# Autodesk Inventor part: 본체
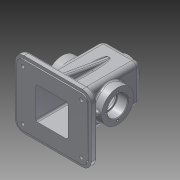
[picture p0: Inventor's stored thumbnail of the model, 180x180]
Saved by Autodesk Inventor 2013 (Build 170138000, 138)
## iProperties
Created: 2016-01
Part Number: 본체
Material: 알루미늄 6061
Document SubType Name: Modeling
Designer: User
Density: 2.71 g/cm^3
Mass: 889.915 g
Surface Area: 961.713 cm^2
Volume: 328.382 cm^3
Author: User
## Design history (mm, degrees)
sketch "스케치1"
  geometry: L1 (-32.5, 55)-(32.5, 55); L2 (32.5, 55)-(32.5, -55); L3 (32.5, -55)-(-32.5, -55); L4 (-32.5, -55)-(-32.5, 55); 1 further point
  constraints: 8 end point, 2 parallel, 1 horizontal, 1 perpendicular
  dimensions: "d0" = 65 distance of L1.start L1.end; "d2" = 110 distance of L3.end L1.start; "d3" = 32.5 distance from line of point (0, 0) L4; "d4" = 55 distance from line of point (0, 0) L1
extrude "돌출1" new body sketch "스케치1" stored distance "d5" = 65; taper "d6" = 0 deg
sketch "스케치2"
  geometry: L1 (65, 0)-(65, -65) reference; L2 (0, 0)-(65, 0) reference; L3 (0, 0)-(0, -65) reference; L4 (65, -65)-(0, -65) reference; L5 (5, -5)-(60, -5); L6 (60, -5)-(60, -60); L7 (60, -60)-(5, -60); L8 (5, -60)-(5, -5); 1 further point
  constraints: 8 end point, 2 parallel, 1 horizontal, 1 perpendicular
  dimensions: "d7" = 5 distance between parallel lines of L8 L3; "d8" = 5 distance between parallel lines of L2 L5; "d9" = 5 distance between parallel lines of L1 L6; "d10" = 5 distance between parallel lines of L4 L7
extrude "돌출2" cut sketch "스케치2" distance "d11" = 105; taper "d12" = 0 deg
node "작업 평면1"
sketch "스케치3"
  geometry: C1 r 20 at (32.5, 32.5); 1 further point
  constraints: 1 centre point, 1 coincident
  dimensions: "d14" = 40 diameter of C1
extrude "돌출3" join sketch "스케치3" stored distance "d15" = 105; taper "d16" = 0 deg
hole "구멍1" diameter "d19" = 21; stored, may be unused: countersink angle "d23" = 90 deg, drill point angle "d25" = 118 deg; dims "d17" = 10, "d18" = 10, "d20" = 6, "d21" = 4, "d22" = 2, "d24" = 8
node "작업 평면2"
sketch "스케치5"
  geometry: C1 r 27.5 at (32.5, 55); 1 further point
  constraints: 1 centre point, 1 coincident
  dimensions: "d28" = 55 diameter of C1
extrude "돌출4" join sketch "스케치5" stored distance "d29" = 105; taper "d30" = 0 deg
hole "구멍2" diameter "d33" = 35; stored, may be unused: countersink angle "d37" = 90 deg, drill point angle "d39" = 0 deg; dims "d31" = 10, "d32" = 10, "d34" = 6, "d35" = 4, "d36" = 2, "d38" = 17
hole "구멍3" diameter "d42" = 30; stored, may be unused: countersink angle "d46" = 90 deg, drill point angle "d48" = 0 deg; dims "d40" = 10, "d41" = 10, "d43" = 6, "d44" = 4, "d45" = 2, "d47" = 17
node "작업 평면3"
sketch "스케치6"
  geometry: L1 (-65, 57.5)-(65, 57.5); L2 (65, 57.5)-(65, -57.5); L3 (65, -57.5)-(-65, -57.5); L4 (-65, -57.5)-(-65, 57.5); 1 further point
  constraints: 8 end point, 2 parallel, 1 horizontal, 1 perpendicular
  dimensions: "d50" = 130 distance of L1.start L1.end; "d52" = 115 distance of L1.end L2.end; "d53" = 65 distance from line of point (0, 0) L4; "d54" = 57.5 distance from line of point (0, 0) L1
extrude "돌출5" join sketch "스케치6" distance "d55" = 10; taper "d56" = 0 deg
node "작업 평면4"
sketch "스케치8"
  geometry: L1 (-60, 52.5)-(60, 52.5); L2 (60, 52.5)-(60, -52.5); L3 (60, -52.5)-(-60, -52.5); L4 (-60, -52.5)-(-60, 52.5); L5 (65, -57.5)-(65, 57.5) reference; L6 (65, 57.5)-(-65, 57.5) reference; L7 (-27.5, 27.5)-(27.5, 27.5); L8 (27.5, 27.5)-(27.5, -27.5); L9 (27.5, -27.5)-(-27.5, -27.5); L10 (-27.5, -27.5)-(-27.5, 27.5); 1 further point
  constraints: 16 end point, 4 parallel, 2 horizontal, 2 perpendicular
  dimensions: "d61" = 120 distance of L1.start L1.end; "d63" = 105 distance of L1.end L2.end; "d64" = 5 distance between parallel lines of L5 L2; "d65" = 5 distance between parallel lines of L6 L1; "d66" = 55 distance of L7.start L7.end; "d67" = 55 distance of L7.end L8.end; "d68" = 27.5 distance from line of point (0, 0) L7; "d70" = 27.5 distance from line of point (0, 0) L10
extrude "돌출6" join sketch "스케치8" stored distance "d71" = 10; taper "d72" = 0 deg
extrude "돌출7" cut sketch "스케치8" distance "d73" = 89.75; taper "d74" = 0 deg
sketch "스케치9"
  geometry: L1 (-53, 57.5)-(-63, 57.5) reference; L2 (-53, 57.5)-(-53, -57.5) reference; L3 (55, 32.5)-(-53, 32.5) reference; L4 (-53, 47.5)-(32.069, 32.5); 1 further point
  constraints: 2 end point, 2 point on line
  dimensions: "d79" = 10 distance from line of L1 L4.start; "d80" = 10 deg angle of L1 L4
feature "리브1" sketch "스케치9" dims "d81" = 1, "d82" = 10, "d83" = 0, "d84" = 0, "d85" = 1, "d86" = 1
sketch "스케치11"
  geometry: L1 (-27.5, -65)-(-27.5, 50) reference; L2 (-65, -53)-(65, -53) reference; L3 (-42.5, -53)-(-42.5, -22.279); 1 further point
  constraints: 2 end point, 1 perpendicular, 1 point on line
  dimensions: "d87" = 15 distance from line of L1 L3.start
feature "리브2" sketch "스케치11" dims "d88" = 1, "d89" = 6, "d90" = 0, "d91" = 0, "d92" = 1, "d93" = 1
sketch "스케치12"
  geometry: L1 (-65, 57.5)-(65, 57.5) reference; C1 r 7.5 at (-50, 42.5); C2 r 7.5 at (50, 42.5); C3 r 7.5 at (50, -42.5); C4 r 7.5 at (-50, -42.5); 1 further point
  constraints: 4 centre point, 1 horizontal alignment
  dimensions: "d94" = 15 diameter of C1; "d95" = 15 diameter of C2; "d96" = 15 diameter of C3; "d97" = 15 diameter of C4; "d99" = 15 distance from line of C1.centre L1; "d100" = 100 distance of C2.centre C1.centre; "d102" = 85 distance of C4.centre C1.centre; "d103" = 100 distance of C3.centre C4.centre; "d105" = 42.5 vertical distance of point (0, 0) C2.centre; "d106" = 50 horizontal distance of C3.centre point (0, 0); "d187" = 50 horizontal distance of point (0, 0) C1.centre
extrude "돌출8" join sketch "스케치12" distance "d107" = 3; taper "d108" = 0 deg
hole "구멍4" diameter "d111" = 6; stored, may be unused: countersink angle "d115" = 90 deg, drill point angle "d117" = 0 deg; dims "d109" = 10, "d110" = 10, "d112" = 6, "d113" = 4, "d114" = 2, "d116" = 17
hole "구멍5" diameter "d120" = 6; stored, may be unused: countersink angle "d124" = 90 deg, drill point angle "d126" = 0 deg; dims "d118" = 10, "d119" = 10, "d121" = 6, "d122" = 4, "d123" = 2, "d125" = 17
hole "구멍6" diameter "d129" = 6; stored, may be unused: countersink angle "d133" = 90 deg, drill point angle "d135" = 0 deg; dims "d127" = 10, "d128" = 10, "d130" = 6, "d131" = 4, "d132" = 2, "d134" = 17
hole "구멍7" diameter "d138" = 6; stored, may be unused: countersink angle "d142" = 90 deg, drill point angle "d144" = 0 deg; dims "d136" = 10, "d137" = 10, "d139" = 6, "d140" = 4, "d141" = 2, "d143" = 17
node "작업 평면7"
feature "면 기울기1" dims angle "d145" = 5 deg
sketch "스케치13"
  geometry: L1 (-78.073, 0)-(132.155, 0); C1 r 10.5 at (0, 0) reference; C2 r 20 at (0, 0) reference; C3 r 1.5 at (0, 14.5); C4 r 1.5 at (-14.5, 0); C5 r 1.5 at (0, -14.5); C6 r 1.5 at (14.5, 0)
  constraints: 4 centre point, 2 end point, 1 horizontal, 1 point on line, 1 vertical alignment, 9 other
  dimensions: "d146" = 3 diameter of C3; "d147" = 29 diameter of C3.centre L1; "d150" = 360 deg dimension on C2.centre C3.centre (derived)
hole "구멍8" sketch "스케치13" at (-14.5, 0), (0, 14.5), (14.5, 0), (0, -14.5) diameter "d152" = 2.459; stored, may be unused: countersink angle "d156" = 90 deg, drill point angle "d158" = 118 deg; dims "d153" = 7, "d154" = 4, "d155" = 2, "d157" = 9
sketch "스케치14"
  geometry: L1 (-64.422, 0)-(123.164, 0); C1 r 27.5 at (0, 0) reference; C2 r 2 at (0, 21); C3 r 2 at (-21, 0); C4 r 2 at (0, -21); C5 r 2 at (21, 0)
  constraints: 4 centre point, 2 end point, 1 horizontal, 1 point on line, 1 vertical alignment, 9 other
  dimensions: "d159" = 4 diameter of C2; "d160" = 42 diameter of C2.centre L1; "d163" = 360 deg dimension on C1.centre C2.centre (derived)
hole "구멍9" sketch "스케치14" at (0, 21), (21, 0), (0, -21), (-21, 0) diameter "d165" = 3.242; stored, may be unused: countersink angle "d169" = 90 deg, drill point angle "d171" = 118 deg; dims "d166" = 8, "d167" = 4, "d168" = 2, "d170" = 10
fillet "모깎기1" dims "d172" = 15
fillet "모깎기2" dims "d173" = 3
fillet "모깎기3" dims "d174" = 8
fillet "모깎기5" dims "d176" = 8
fillet "모깎기6" dims "d177" = 3
fillet "모깎기7" dims "d178" = 3
chamfer "모따기1" distance "d179" = 1; stored, may be unused: second distance "d180" = 2, angle "d181" = 45 deg
fillet "모깎기8" dims "d185" = 3
sketch "스케치15"
  geometry: L1 (4.5, 18)-(44.5, 18) reference; L2 (-8, 0)-(-8, -97) reference; 1 further point
  constraints: 1 other
  dimensions: "d188" = 26 distance from line of point (24.5, -8) L1; "d189" = 32.5 distance from line of L2 point (24.5, -8)
feature "엠보싱1" sketch "스케치15" dims "d190" = 0.5, "d191" = 0
fillet "모깎기10" dims "d192" = 3
fillet "모깎기11" dims "d196" = 0.3
fillet "모깎기13" dims "d198" = 10
node "솔리드1"
mirror "대칭1"
mirror "대칭2"
mirror "대칭3"
mirror "대칭4"
other parameters: "d27" = 15, "d49" = -53, "d60" = 2
